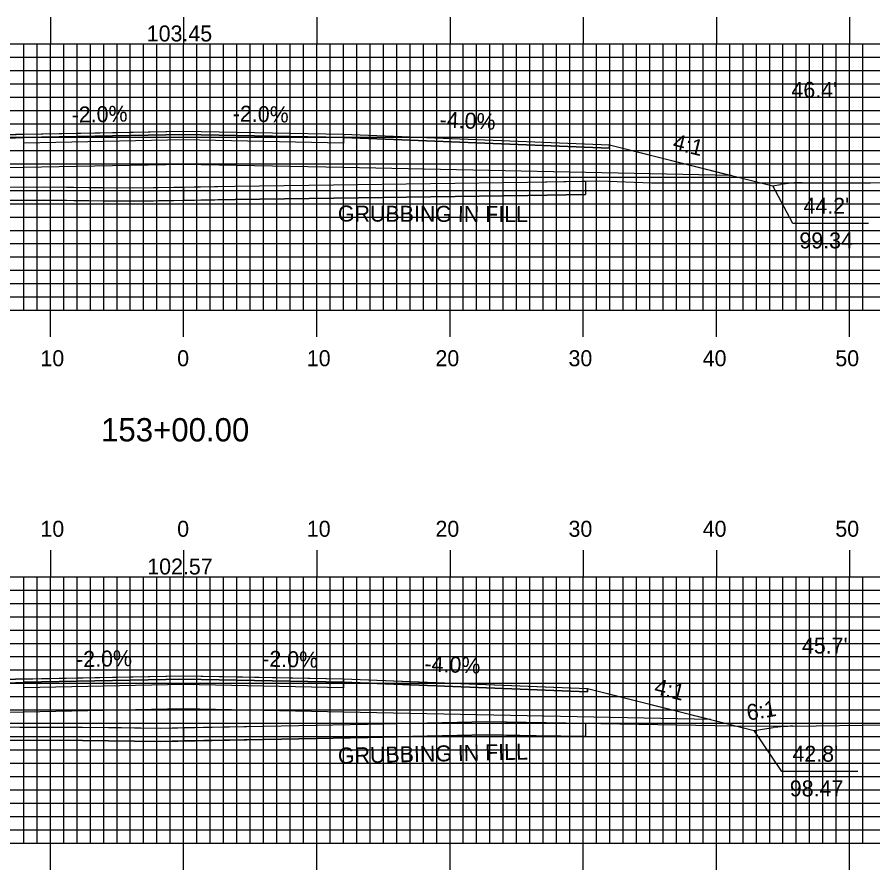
# Model space of a CAD drawing. Extents: x 1778712 to 1779055, y 442591 to 442811.
# Drawn here: x 1778865.3 to 1778929.6, y 442686.7 to 442750.7 of the extents above; entities that cross this region are included whole.
import ezdxf

# ---------------------------------------------------------------- set-up
doc = ezdxf.new("R2010")
doc.units = 0
for name, color, linetype in [('ANNOTATION', 7, 'Continuous'), ('D_Roadway_Centerline', 7, 'Continuous'), ('D_Roadway_Centerline_Text', 7, 'Continuous'), ('D_Roadway_Edge_Shoulder', 7, 'Continuous'), ('D_Roadway_Edge_TW', 7, 'Continuous'), ('D_Roadway_Pavement', 7, 'Continuous'), ('D_Roadway_SlopeLines', 7, 'Continuous'), ('D_Roadway_SubGrade', 7, 'Continuous'), ('D_Text_Standard', 7, 'Continuous'), ('GRUBBING IN FILL', 7, 'Continuous'), ('H_V ANNOTATION', 7, 'Continuous'), ('MAJOR', 7, 'Continuous'), ('MINOR', 7, 'Continuous'), ('S_Roadway_Centerline', 7, 'Continuous')]:
    doc.layers.add(name, color=color, linetype=linetype)

msp = doc.modelspace()

# ---------------------------------------------------------------- linework, layer by layer
at = {"layer": 'ANNOTATION'}
for points in [[(1778929.236, 442735.183), (1778923.544, 442735.183), (1778922.053, 442738.009)], [(1778928.43, 442694.052), (1778922.739, 442694.052), (1778920.657, 442697.134)]]:
    msp.add_lwpolyline(points, dxfattribs=at)
at = {"layer": 'D_Roadway_Centerline'}
for points in [[(1778843.141, 442737.884), (1778845.246, 442738.41), (1778845.816, 442738.552), (1778846.159, 442738.638), (1778847.642, 442739.009), (1778857.816, 442741.552), (1778860.631, 442741.665), (1778865.816, 442741.872), (1778871.523, 442741.986), (1778877.816, 442742.112), (1778889.816, 442741.872), (1778909.797, 442741.073)], [(1778842.737, 442696.908), (1778845.816, 442697.677), (1778847.142, 442698.009), (1778847.643, 442698.134), (1778857.816, 442700.677), (1778865.816, 442700.997), (1778866.485, 442701.011), (1778877.816, 442701.237), (1778882.23, 442701.149), (1778889.816, 442700.997), (1778896.708, 442700.722), (1778908.134, 442700.264), (1778917.409, 442697.946)]]:
    msp.add_lwpolyline(points, dxfattribs=at)
at = {"layer": 'D_Roadway_Edge_Shoulder'}
for points in [[(1778865.816, 442741.872), (1778857.816, 442741.552), (1778857.816, 442741.302), (1778865.816, 442741.622)], [(1778889.816, 442741.872), (1778909.797, 442741.073), (1778909.797, 442740.823), (1778889.816, 442741.622)], [(1778865.816, 442700.997), (1778857.816, 442700.677), (1778857.816, 442700.427), (1778865.816, 442700.747)], [(1778889.816, 442700.997), (1778908.134, 442700.264), (1778908.134, 442700.014), (1778889.816, 442700.747)]]:
    msp.add_lwpolyline(points, close=True, dxfattribs=at)
at = {"layer": 'D_Roadway_Edge_TW'}
for points in [[(1778865.816, 442741.622), (1778865.816, 442741.872), (1778877.816, 442742.112), (1778889.816, 442741.872), (1778889.816, 442741.622), (1778877.816, 442741.862)], [(1778865.816, 442700.747), (1778865.816, 442700.997), (1778877.816, 442701.237), (1778889.816, 442700.997), (1778889.816, 442700.747), (1778877.816, 442700.987)]]:
    msp.add_lwpolyline(points, close=True, dxfattribs=at)
at = {"layer": 'D_Roadway_Pavement'}
for points in [[(1778865.816, 442741.206), (1778865.816, 442741.622), (1778877.816, 442741.862), (1778889.816, 442741.622), (1778889.816, 442741.206), (1778877.816, 442741.446)], [(1778865.816, 442700.331), (1778865.816, 442700.747), (1778877.816, 442700.987), (1778889.816, 442700.747), (1778889.816, 442700.331), (1778877.816, 442700.571)]]:
    msp.add_lwpolyline(points, close=True, dxfattribs=at)
at = {"layer": 'D_Roadway_SlopeLines'}
msp.add_line((1778922.053, 442738.009), (1778922.618, 442738.103), dxfattribs=at)
for points in [[(1778909.797, 442741.073), (1778922.053, 442738.009)], [(1778908.134, 442700.264), (1778920.657, 442697.134)], [(1778920.657, 442697.134), (1778922.073, 442697.338)]]:
    msp.add_lwpolyline(points, dxfattribs=at)
for centre, start, end in [((1778924.262, 442728.239), 89.98596, 99.46232), ((1778923.496, 442687.44), 89.72732, 98.18406)]:
    msp.add_arc(centre, 10, start, end, dxfattribs=at)
at = {"layer": 'D_Roadway_SubGrade'}
for points in [[(1778865.816, 442739.372), (1778847.642, 442739.009), (1778857.816, 442741.552), (1778857.816, 442741.302), (1778865.816, 442741.622), (1778877.816, 442741.862), (1778889.816, 442741.622), (1778909.797, 442740.823), (1778909.797, 442741.073), (1778918.927, 442738.791), (1778889.816, 442739.372), (1778877.816, 442739.612)], [(1778865.816, 442698.497), (1778847.643, 442698.134), (1778857.816, 442700.677), (1778857.816, 442700.427), (1778865.816, 442700.747), (1778877.816, 442700.987), (1778889.816, 442700.747), (1778908.134, 442700.014), (1778908.134, 442700.264), (1778917.409, 442697.946), (1778889.816, 442698.497), (1778877.816, 442698.737)]]:
    msp.add_lwpolyline(points, close=True, dxfattribs=at)
at = {"layer": 'GRUBBING IN FILL'}
for p, q in [((1778907.989, 442738.356), (1778907.989, 442737.356)), ((1778907.989, 442738.356), (1778907.989, 442737.356)), ((1778907.99, 442697.667), (1778907.99, 442696.666)), ((1778907.99, 442697.667), (1778907.99, 442696.666))]:
    msp.add_line(p, q, dxfattribs=at)
for points in [[(1778847.642, 442737.799), (1778850.644, 442737.739), (1778856.664, 442737.842), (1778862.003, 442737.881), (1778867.341, 442737.92), (1778870.689, 442737.882), (1778874.037, 442737.843), (1778877.816, 442737.91), (1778877.816, 442736.91), (1778874.04, 442736.843), (1778870.69, 442736.882), (1778867.339, 442736.92), (1778862.008, 442736.881), (1778856.676, 442736.842), (1778850.643, 442736.739), (1778847.642, 442736.798)], [(1778847.642, 442737.799), (1778850.644, 442737.739), (1778856.664, 442737.842), (1778862.003, 442737.881), (1778867.341, 442737.92), (1778870.689, 442737.882), (1778874.037, 442737.843), (1778877.816, 442737.91), (1778877.816, 442736.91), (1778874.04, 442736.843), (1778870.69, 442736.882), (1778867.339, 442736.92), (1778862.008, 442736.881), (1778856.676, 442736.842), (1778850.643, 442736.739), (1778847.642, 442736.798)], [(1778877.816, 442737.91), (1778881.664, 442737.978), (1778889.073, 442738.075), (1778896.352, 442738.174), (1778903.631, 442738.274), (1778907.989, 442738.356), (1778907.989, 442737.356), (1778903.647, 442737.274), (1778896.367, 442737.174), (1778889.086, 442737.075), (1778881.679, 442736.978), (1778877.816, 442736.91)], [(1778877.816, 442737.91), (1778881.664, 442737.978), (1778889.073, 442738.075), (1778896.352, 442738.174), (1778903.631, 442738.274), (1778907.989, 442738.356), (1778907.989, 442737.356), (1778903.647, 442737.274), (1778896.367, 442737.174), (1778889.086, 442737.075), (1778881.679, 442736.978), (1778877.816, 442736.91)], [(1778847.643, 442695.928), (1778847.643, 442696.928), (1778856.901, 442697.228), (1778860.796, 442697.389), (1778865.513, 442697.382), (1778873.154, 442697.34), (1778876.078, 442697.307), (1778877.816, 442697.339), (1778877.816, 442696.339), (1778876.081, 442696.307), (1778870.223, 442696.374), (1778865.52, 442696.382), (1778860.816, 442696.389), (1778856.93, 442696.228), (1778851.651, 442696.014), (1778850.184, 442695.961), (1778848.95, 442695.945)], [(1778847.643, 442695.928), (1778847.643, 442696.928), (1778856.901, 442697.228), (1778860.796, 442697.389), (1778865.513, 442697.382), (1778873.154, 442697.34), (1778876.078, 442697.307), (1778877.816, 442697.339), (1778877.816, 442696.339), (1778876.081, 442696.307), (1778870.223, 442696.374), (1778865.52, 442696.382), (1778860.816, 442696.389), (1778856.93, 442696.228), (1778851.651, 442696.014), (1778850.184, 442695.961), (1778848.95, 442695.945)], [(1778877.816, 442697.339), (1778883.851, 442697.453), (1778891.625, 442697.599), (1778896.101, 442697.702), (1778900.578, 442697.804), (1778907.99, 442697.667), (1778907.99, 442696.666), (1778904.285, 442696.735), (1778900.58, 442696.804), (1778896.113, 442696.702), (1778891.645, 442696.6), (1778883.863, 442696.453), (1778877.816, 442696.339)], [(1778877.816, 442697.339), (1778883.851, 442697.453), (1778891.625, 442697.599), (1778896.101, 442697.702), (1778900.578, 442697.804), (1778907.99, 442697.667), (1778907.99, 442696.666), (1778904.285, 442696.735), (1778900.58, 442696.804), (1778896.113, 442696.702), (1778891.645, 442696.6), (1778883.863, 442696.453), (1778877.816, 442696.339)]]:
    msp.add_lwpolyline(points, close=True, dxfattribs=at)
for points in [[(1778847.642, 442736.798), (1778850.643, 442736.739), (1778856.676, 442736.842), (1778867.339, 442736.92), (1778874.04, 442736.843), (1778881.679, 442736.978), (1778889.086, 442737.075), (1778903.647, 442737.274), (1778907.989, 442737.356)], [(1778847.642, 442736.798), (1778850.643, 442736.739), (1778856.676, 442736.842), (1778867.339, 442736.92), (1778874.04, 442736.843), (1778881.679, 442736.978), (1778889.086, 442737.075), (1778903.647, 442737.274), (1778907.989, 442737.356)], [(1778847.643, 442695.928), (1778850.258, 442695.962), (1778853.045, 442696.067), (1778860.816, 442696.389), (1778870.223, 442696.374), (1778876.081, 442696.307), (1778891.645, 442696.6), (1778900.58, 442696.804), (1778907.99, 442696.666)], [(1778847.643, 442695.928), (1778850.258, 442695.962), (1778853.045, 442696.067), (1778860.816, 442696.389), (1778870.223, 442696.374), (1778876.081, 442696.307), (1778891.645, 442696.6), (1778900.58, 442696.804), (1778907.99, 442696.666)]]:
    msp.add_lwpolyline(points, dxfattribs=at)
at = {"layer": 'MAJOR'}
for p, q in [((1778867.816, 442750.669), (1778867.816, 442748.665)), ((1778877.816, 442750.669), (1778877.816, 442748.665)), ((1778887.816, 442750.669), (1778887.816, 442748.665)), ((1778897.816, 442750.669), (1778897.816, 442748.665)), ((1778907.816, 442750.669), (1778907.816, 442748.665)), ((1778917.816, 442750.669), (1778917.816, 442748.665)), ((1778927.816, 442750.669), (1778927.816, 442748.665)), ((1778737.816, 442748.665), (1779017.816, 442748.665)), ((1778737.816, 442748.665), (1779017.816, 442748.665)), ((1778867.816, 442728.665), (1778867.816, 442748.665)), ((1778877.816, 442728.665), (1778877.816, 442748.665)), ((1778887.816, 442728.665), (1778887.816, 442748.665)), ((1778897.816, 442728.665), (1778897.816, 442748.665)), ((1778907.816, 442728.665), (1778907.816, 442748.665)), ((1778917.816, 442728.665), (1778917.816, 442748.665)), ((1778927.816, 442728.665), (1778927.816, 442748.665)), ((1778737.816, 442743.665), (1779017.816, 442743.665)), ((1778737.816, 442738.665), (1779017.816, 442738.665)), ((1778737.816, 442733.665), (1779017.816, 442733.665)), ((1778737.816, 442728.665), (1779017.816, 442728.665)), ((1778737.816, 442728.665), (1779017.816, 442728.665)), ((1778867.816, 442726.661), (1778867.816, 442728.665)), ((1778877.816, 442726.661), (1778877.816, 442728.665)), ((1778887.816, 442726.661), (1778887.816, 442728.665)), ((1778897.816, 442726.661), (1778897.816, 442728.665)), ((1778907.816, 442726.661), (1778907.816, 442728.665)), ((1778917.816, 442726.661), (1778917.816, 442728.665)), ((1778927.816, 442726.661), (1778927.816, 442728.665)), ((1778867.816, 442710.669), (1778867.816, 442708.665)), ((1778877.816, 442710.669), (1778877.816, 442708.665)), ((1778887.816, 442710.669), (1778887.816, 442708.665)), ((1778897.816, 442710.669), (1778897.816, 442708.665)), ((1778907.816, 442710.669), (1778907.816, 442708.665)), ((1778917.816, 442710.669), (1778917.816, 442708.665)), ((1778927.816, 442710.669), (1778927.816, 442708.665)), ((1778737.816, 442708.665), (1779017.816, 442708.665)), ((1778737.816, 442708.665), (1779017.816, 442708.665)), ((1778867.816, 442688.665), (1778867.816, 442708.665)), ((1778877.816, 442688.665), (1778877.816, 442708.665)), ((1778887.816, 442688.665), (1778887.816, 442708.665)), ((1778897.816, 442688.665), (1778897.816, 442708.665)), ((1778907.816, 442688.665), (1778907.816, 442708.665)), ((1778917.816, 442688.665), (1778917.816, 442708.665)), ((1778927.816, 442688.665), (1778927.816, 442708.665)), ((1778737.816, 442703.665), (1779017.816, 442703.665)), ((1778737.816, 442698.665), (1779017.816, 442698.665)), ((1778737.816, 442693.665), (1779017.816, 442693.665)), ((1778737.816, 442688.665), (1779017.816, 442688.665)), ((1778737.816, 442688.665), (1779017.816, 442688.665)), ((1778867.816, 442686.661), (1778867.816, 442688.665)), ((1778877.816, 442686.661), (1778877.816, 442688.665)), ((1778887.816, 442686.661), (1778887.816, 442688.665)), ((1778897.816, 442686.661), (1778897.816, 442688.665)), ((1778907.816, 442686.661), (1778907.816, 442688.665)), ((1778917.816, 442686.661), (1778917.816, 442688.665)), ((1778927.816, 442686.661), (1778927.816, 442688.665))]:
    msp.add_line(p, q, dxfattribs=at)
at = {"layer": 'MINOR'}
for p, q in [((1778865.816, 442728.665), (1778865.816, 442748.665)), ((1778866.816, 442728.665), (1778866.816, 442748.665)), ((1778868.816, 442728.665), (1778868.816, 442748.665)), ((1778869.816, 442728.665), (1778869.816, 442748.665)), ((1778870.816, 442728.665), (1778870.816, 442748.665)), ((1778871.816, 442728.665), (1778871.816, 442748.665)), ((1778872.816, 442728.665), (1778872.816, 442748.665)), ((1778873.816, 442728.665), (1778873.816, 442748.665)), ((1778874.816, 442728.665), (1778874.816, 442748.665)), ((1778875.816, 442728.665), (1778875.816, 442748.665)), ((1778876.816, 442728.665), (1778876.816, 442748.665)), ((1778878.816, 442728.665), (1778878.816, 442748.665)), ((1778879.816, 442728.665), (1778879.816, 442748.665)), ((1778880.816, 442728.665), (1778880.816, 442748.665)), ((1778881.816, 442728.665), (1778881.816, 442748.665)), ((1778882.816, 442728.665), (1778882.816, 442748.665)), ((1778883.816, 442728.665), (1778883.816, 442748.665)), ((1778884.816, 442728.665), (1778884.816, 442748.665)), ((1778885.816, 442728.665), (1778885.816, 442748.665)), ((1778886.816, 442728.665), (1778886.816, 442748.665)), ((1778888.816, 442728.665), (1778888.816, 442748.665)), ((1778889.816, 442728.665), (1778889.816, 442748.665)), ((1778890.816, 442728.665), (1778890.816, 442748.665)), ((1778891.816, 442728.665), (1778891.816, 442748.665)), ((1778892.816, 442728.665), (1778892.816, 442748.665)), ((1778893.816, 442728.665), (1778893.816, 442748.665)), ((1778894.816, 442728.665), (1778894.816, 442748.665)), ((1778895.816, 442728.665), (1778895.816, 442748.665)), ((1778896.816, 442728.665), (1778896.816, 442748.665)), ((1778898.816, 442728.665), (1778898.816, 442748.665)), ((1778899.816, 442728.665), (1778899.816, 442748.665)), ((1778900.816, 442728.665), (1778900.816, 442748.665)), ((1778901.816, 442728.665), (1778901.816, 442748.665)), ((1778902.816, 442728.665), (1778902.816, 442748.665)), ((1778903.816, 442728.665), (1778903.816, 442748.665)), ((1778904.816, 442728.665), (1778904.816, 442748.665)), ((1778905.816, 442728.665), (1778905.816, 442748.665)), ((1778906.816, 442728.665), (1778906.816, 442748.665)), ((1778908.816, 442728.665), (1778908.816, 442748.665)), ((1778909.816, 442728.665), (1778909.816, 442748.665)), ((1778910.816, 442728.665), (1778910.816, 442748.665)), ((1778911.816, 442728.665), (1778911.816, 442748.665)), ((1778912.816, 442728.665), (1778912.816, 442748.665)), ((1778913.816, 442728.665), (1778913.816, 442748.665)), ((1778914.816, 442728.665), (1778914.816, 442748.665)), ((1778915.816, 442728.665), (1778915.816, 442748.665)), ((1778916.816, 442728.665), (1778916.816, 442748.665)), ((1778918.816, 442728.665), (1778918.816, 442748.665)), ((1778919.816, 442728.665), (1778919.816, 442748.665)), ((1778920.816, 442728.665), (1778920.816, 442748.665)), ((1778921.816, 442728.665), (1778921.816, 442748.665)), ((1778922.816, 442728.665), (1778922.816, 442748.665)), ((1778923.816, 442728.665), (1778923.816, 442748.665)), ((1778924.816, 442728.665), (1778924.816, 442748.665)), ((1778925.816, 442728.665), (1778925.816, 442748.665)), ((1778926.816, 442728.665), (1778926.816, 442748.665)), ((1778928.816, 442728.665), (1778928.816, 442748.665)), ((1778737.816, 442747.665), (1779017.816, 442747.665)), ((1778737.816, 442746.665), (1779017.816, 442746.665)), ((1778737.816, 442745.665), (1779017.816, 442745.665)), ((1778737.816, 442744.665), (1779017.816, 442744.665)), ((1778737.816, 442742.665), (1779017.816, 442742.665)), ((1778737.816, 442741.665), (1779017.816, 442741.665)), ((1778737.816, 442740.665), (1779017.816, 442740.665)), ((1778737.816, 442739.665), (1779017.816, 442739.665)), ((1778737.816, 442737.665), (1779017.816, 442737.665)), ((1778737.816, 442736.665), (1779017.816, 442736.665)), ((1778737.816, 442735.665), (1779017.816, 442735.665)), ((1778737.816, 442734.665), (1779017.816, 442734.665)), ((1778737.816, 442732.665), (1779017.816, 442732.665)), ((1778737.816, 442731.665), (1779017.816, 442731.665)), ((1778737.816, 442730.665), (1779017.816, 442730.665)), ((1778737.816, 442729.665), (1779017.816, 442729.665)), ((1778865.816, 442688.665), (1778865.816, 442708.665)), ((1778866.816, 442688.665), (1778866.816, 442708.665)), ((1778868.816, 442688.665), (1778868.816, 442708.665)), ((1778869.816, 442688.665), (1778869.816, 442708.665)), ((1778870.816, 442688.665), (1778870.816, 442708.665)), ((1778871.816, 442688.665), (1778871.816, 442708.665)), ((1778872.816, 442688.665), (1778872.816, 442708.665)), ((1778873.816, 442688.665), (1778873.816, 442708.665)), ((1778874.816, 442688.665), (1778874.816, 442708.665)), ((1778875.816, 442688.665), (1778875.816, 442708.665)), ((1778876.816, 442688.665), (1778876.816, 442708.665)), ((1778878.816, 442688.665), (1778878.816, 442708.665)), ((1778879.816, 442688.665), (1778879.816, 442708.665)), ((1778880.816, 442688.665), (1778880.816, 442708.665)), ((1778881.816, 442688.665), (1778881.816, 442708.665)), ((1778882.816, 442688.665), (1778882.816, 442708.665)), ((1778883.816, 442688.665), (1778883.816, 442708.665)), ((1778884.816, 442688.665), (1778884.816, 442708.665)), ((1778885.816, 442688.665), (1778885.816, 442708.665)), ((1778886.816, 442688.665), (1778886.816, 442708.665)), ((1778888.816, 442688.665), (1778888.816, 442708.665)), ((1778889.816, 442688.665), (1778889.816, 442708.665)), ((1778890.816, 442688.665), (1778890.816, 442708.665)), ((1778891.816, 442688.665), (1778891.816, 442708.665)), ((1778892.816, 442688.665), (1778892.816, 442708.665)), ((1778893.816, 442688.665), (1778893.816, 442708.665)), ((1778894.816, 442688.665), (1778894.816, 442708.665)), ((1778895.816, 442688.665), (1778895.816, 442708.665)), ((1778896.816, 442688.665), (1778896.816, 442708.665)), ((1778898.816, 442688.665), (1778898.816, 442708.665)), ((1778899.816, 442688.665), (1778899.816, 442708.665)), ((1778900.816, 442688.665), (1778900.816, 442708.665)), ((1778901.816, 442688.665), (1778901.816, 442708.665)), ((1778902.816, 442688.665), (1778902.816, 442708.665)), ((1778903.816, 442688.665), (1778903.816, 442708.665)), ((1778904.816, 442688.665), (1778904.816, 442708.665)), ((1778905.816, 442688.665), (1778905.816, 442708.665)), ((1778906.816, 442688.665), (1778906.816, 442708.665)), ((1778908.816, 442688.665), (1778908.816, 442708.665)), ((1778909.816, 442688.665), (1778909.816, 442708.665)), ((1778910.816, 442688.665), (1778910.816, 442708.665)), ((1778911.816, 442688.665), (1778911.816, 442708.665)), ((1778912.816, 442688.665), (1778912.816, 442708.665)), ((1778913.816, 442688.665), (1778913.816, 442708.665)), ((1778914.816, 442688.665), (1778914.816, 442708.665)), ((1778915.816, 442688.665), (1778915.816, 442708.665)), ((1778916.816, 442688.665), (1778916.816, 442708.665)), ((1778918.816, 442688.665), (1778918.816, 442708.665)), ((1778919.816, 442688.665), (1778919.816, 442708.665)), ((1778920.816, 442688.665), (1778920.816, 442708.665)), ((1778921.816, 442688.665), (1778921.816, 442708.665)), ((1778922.816, 442688.665), (1778922.816, 442708.665)), ((1778923.816, 442688.665), (1778923.816, 442708.665)), ((1778924.816, 442688.665), (1778924.816, 442708.665)), ((1778925.816, 442688.665), (1778925.816, 442708.665)), ((1778926.816, 442688.665), (1778926.816, 442708.665)), ((1778928.816, 442688.665), (1778928.816, 442708.665)), ((1778737.816, 442707.665), (1779017.816, 442707.665)), ((1778737.816, 442706.665), (1779017.816, 442706.665)), ((1778737.816, 442705.665), (1779017.816, 442705.665)), ((1778737.816, 442704.665), (1779017.816, 442704.665)), ((1778737.816, 442702.665), (1779017.816, 442702.665)), ((1778737.816, 442701.665), (1779017.816, 442701.665)), ((1778737.816, 442700.665), (1779017.816, 442700.665)), ((1778737.816, 442699.665), (1779017.816, 442699.665)), ((1778737.816, 442697.665), (1779017.816, 442697.665)), ((1778737.816, 442696.665), (1779017.816, 442696.665)), ((1778737.816, 442695.665), (1779017.816, 442695.665)), ((1778737.816, 442694.665), (1779017.816, 442694.665)), ((1778737.816, 442692.665), (1779017.816, 442692.665)), ((1778737.816, 442691.665), (1779017.816, 442691.665)), ((1778737.816, 442690.665), (1779017.816, 442690.665)), ((1778737.816, 442689.665), (1779017.816, 442689.665))]:
    msp.add_line(p, q, dxfattribs=at)
at = {"layer": 'S_Roadway_Centerline'}
for points in [[(1778815.817, 442738.05), (1778821.889, 442738.094), (1778827.538, 442738.091), (1778832.855, 442738.061), (1778844.563, 442737.86), (1778850.644, 442737.739), (1778856.664, 442737.842), (1778867.341, 442737.92), (1778874.037, 442737.843), (1778881.664, 442737.978), (1778889.073, 442738.075), (1778903.631, 442738.274), (1778909.074, 442738.377), (1778912.943, 442738.242), (1778929.396, 442738.238), (1778932.358, 442738.291)], [(1778737.816, 442696.093), (1778746.066, 442696.061), (1778756.188, 442696.432), (1778757.024, 442696.435), (1778779.083, 442696.346), (1778781.608, 442696.381), (1778801.369, 442696.642), (1778805.175, 442696.733), (1778814.744, 442696.936), (1778824.282, 442696.921), (1778826.844, 442696.839), (1778829.092, 442696.851), (1778847.692, 442696.929), (1778850.233, 442696.961), (1778853.005, 442697.067), (1778860.796, 442697.389), (1778870.23, 442697.374), (1778876.078, 442697.307), (1778891.625, 442697.599), (1778900.578, 442697.804), (1778919.12, 442697.461), (1778923.545, 442697.44), (1778930.541, 442697.551)]]:
    msp.add_lwpolyline(points, dxfattribs=at)

# ---------------------------------------------------------------- texts
at = {"layer": 'ANNOTATION'}
for s, rotation, p in [('-2.0%', 1.14576, (1778869.422, 442742.745)), ('-2.0%', 358.85424, (1778881.502, 442742.839)), ('-4.0%', 357.70947, (1778897.021, 442742.386)), ('4:1', 345.96527, (1778914.472, 442740.766)), ('-2.0%', 1.14576, (1778869.757, 442701.876)), ('-2.0%', 358.85424, (1778883.709, 442701.92)), ('-4.0%', 357.70927, (1778895.885, 442701.556)), ('4:1', 345.96596, (1778913.076, 442699.891)), ('6:1', 9.46702, (1778920.185, 442697.859))]:
    msp.add_text(s, height=1.2, rotation=rotation, dxfattribs=at).set_placement(p)
for s, p in [("44.2'", (1778924.354, 442735.909)), ('99.34', (1778924.049, 442733.309)), ("42.8'", (1778923.527, 442694.778)), ('98.47', (1778923.329, 442692.178))]:
    msp.add_text(s, height=1.2, dxfattribs=at).set_placement(p)
at = {"layer": 'D_Roadway_Centerline'}
for s, p in [('C', (1778877.811, 442742.112)), ('L', (1778877.816, 442742.105)), ('C', (1778877.811, 442701.237)), ('L', (1778877.816, 442701.23))]:
    msp.add_text(s, height=0.0146, dxfattribs=at).set_placement(p)
at = {"layer": 'D_Roadway_Centerline_Text'}
for s, p in [('103.45', (1778875.05, 442748.842)), ('102.57', (1778875.087, 442708.833))]:
    msp.add_text(s, height=1.2, dxfattribs=at).set_placement(p)
at = {"layer": 'D_Text_Standard'}
for s, p in [("46.4'", (1778923.452, 442744.61)), ("45.7'", (1778924.241, 442702.902))]:
    msp.add_text(s, height=1.2, dxfattribs=at).set_placement(p)
at = {"layer": 'GRUBBING IN FILL'}
for rotation, p in [(359.80532, (1778889.399, 442735.328)), (1.25684, (1778889.413, 442694.632))]:
    msp.add_text('GRUBBING IN FILL', height=1.2, rotation=rotation, dxfattribs=at).set_placement(p)
at = {"layer": 'H_V ANNOTATION'}
for s, height, p in [('10', 1.2, (1778867.067, 442724.465)), ('0', 1.2, (1778877.334, 442724.465)), ('10', 1.2, (1778887.067, 442724.465)), ('20', 1.2, (1778896.724, 442724.465)), ('30', 1.2, (1778906.713, 442724.465)), ('40', 1.2, (1778916.788, 442724.465)), ('50', 1.2, (1778926.745, 442724.465)), ('153+00.00', 1.75, (1778871.621, 442718.821)), ('10', 1.2, (1778867.067, 442711.665)), ('0', 1.2, (1778877.334, 442711.665)), ('10', 1.2, (1778887.067, 442711.665)), ('20', 1.2, (1778896.724, 442711.665)), ('30', 1.2, (1778906.713, 442711.665)), ('40', 1.2, (1778916.788, 442711.665)), ('50', 1.2, (1778926.745, 442711.665))]:
    msp.add_text(s, height=height, dxfattribs=at).set_placement(p)

doc.saveas('drawing.dxf')
